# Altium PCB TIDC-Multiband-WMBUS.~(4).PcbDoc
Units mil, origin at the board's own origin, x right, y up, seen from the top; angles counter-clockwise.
Board outline 1550.5 x 1401.5 mil, 4 copper layers (1, 2, 3, 4); 57 components, 34 nets, 205 pads, 172 vias.
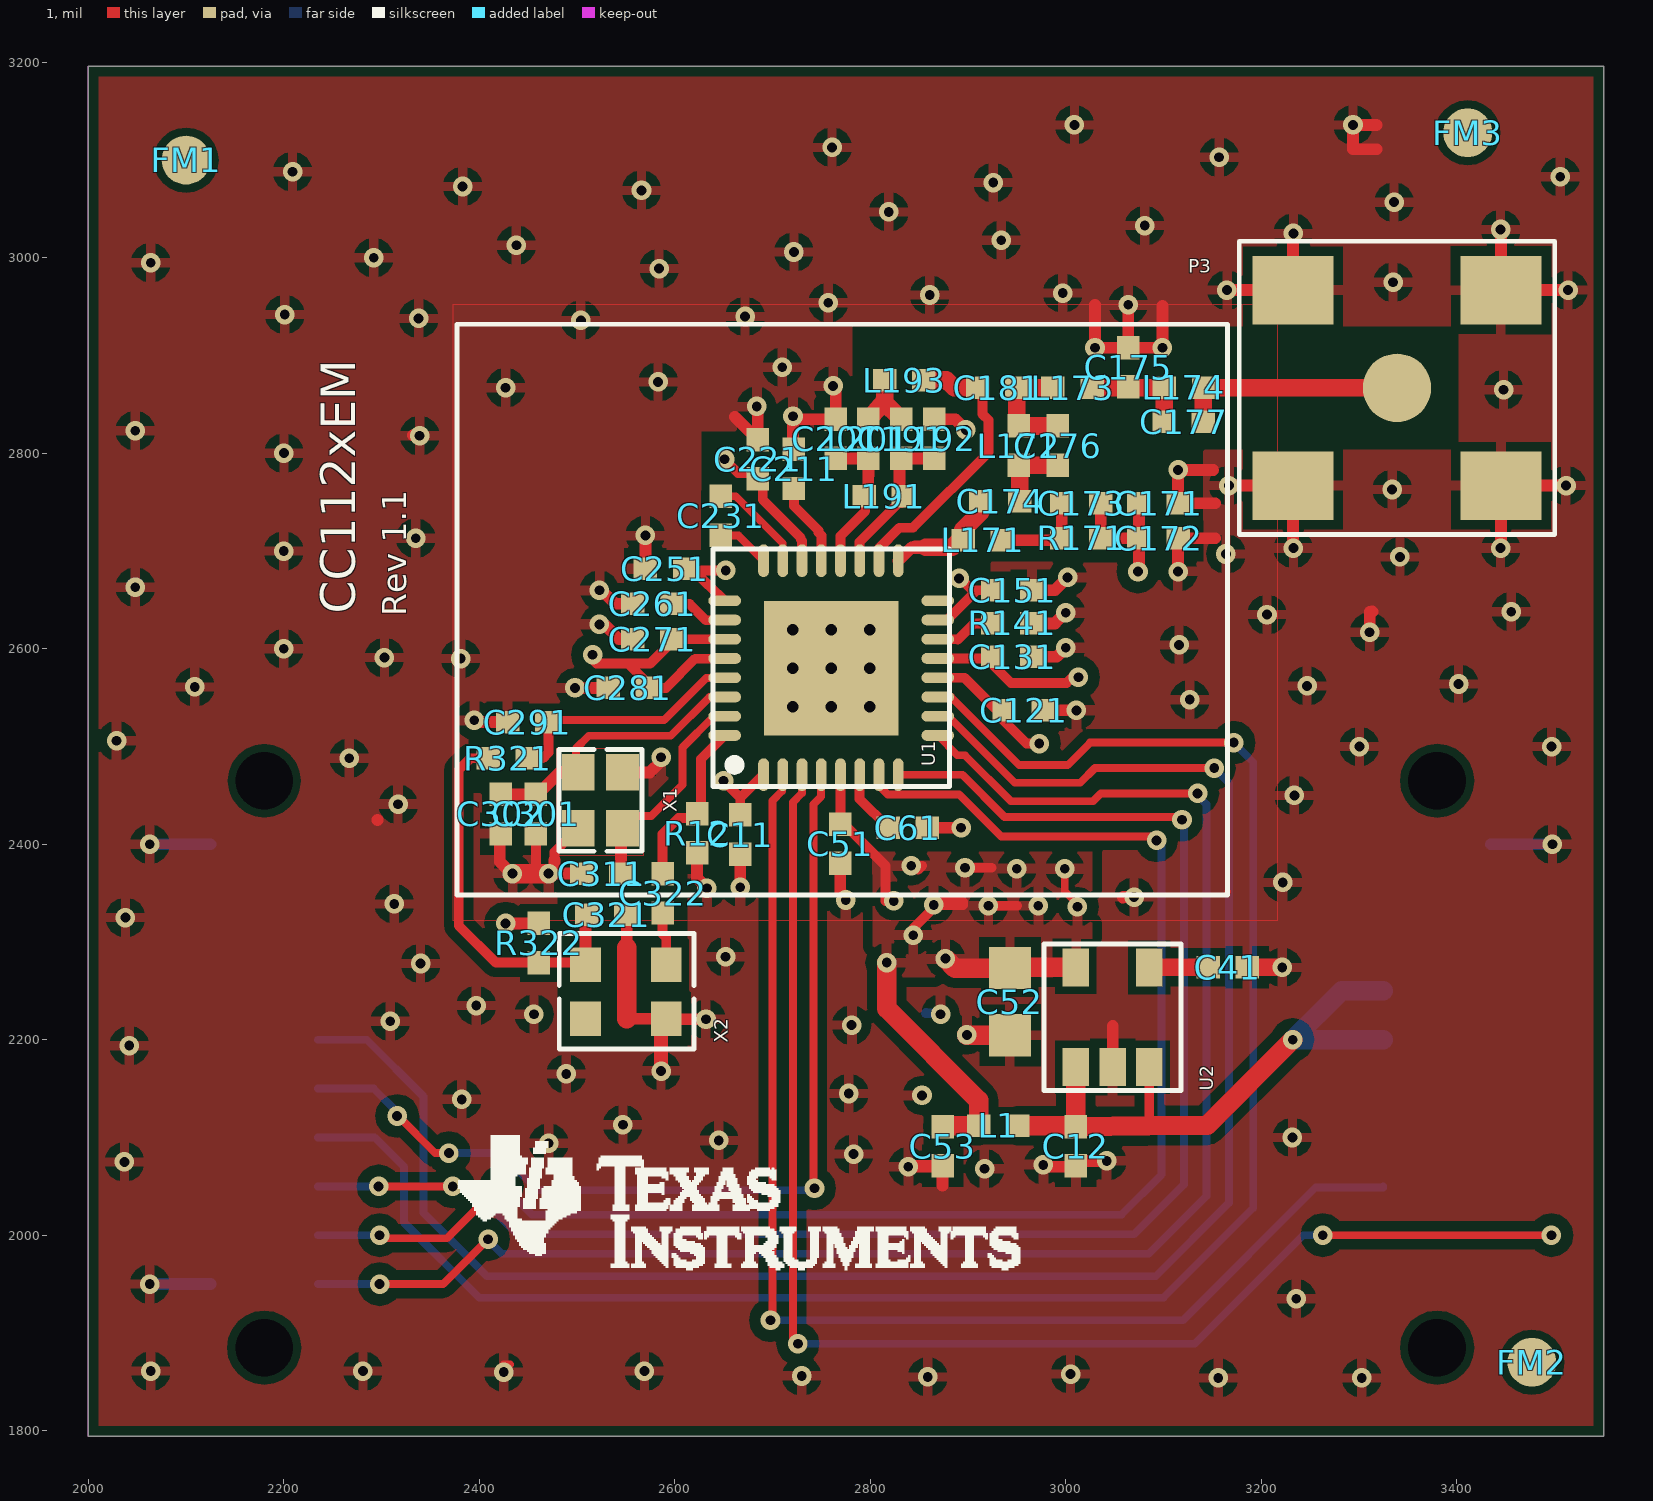
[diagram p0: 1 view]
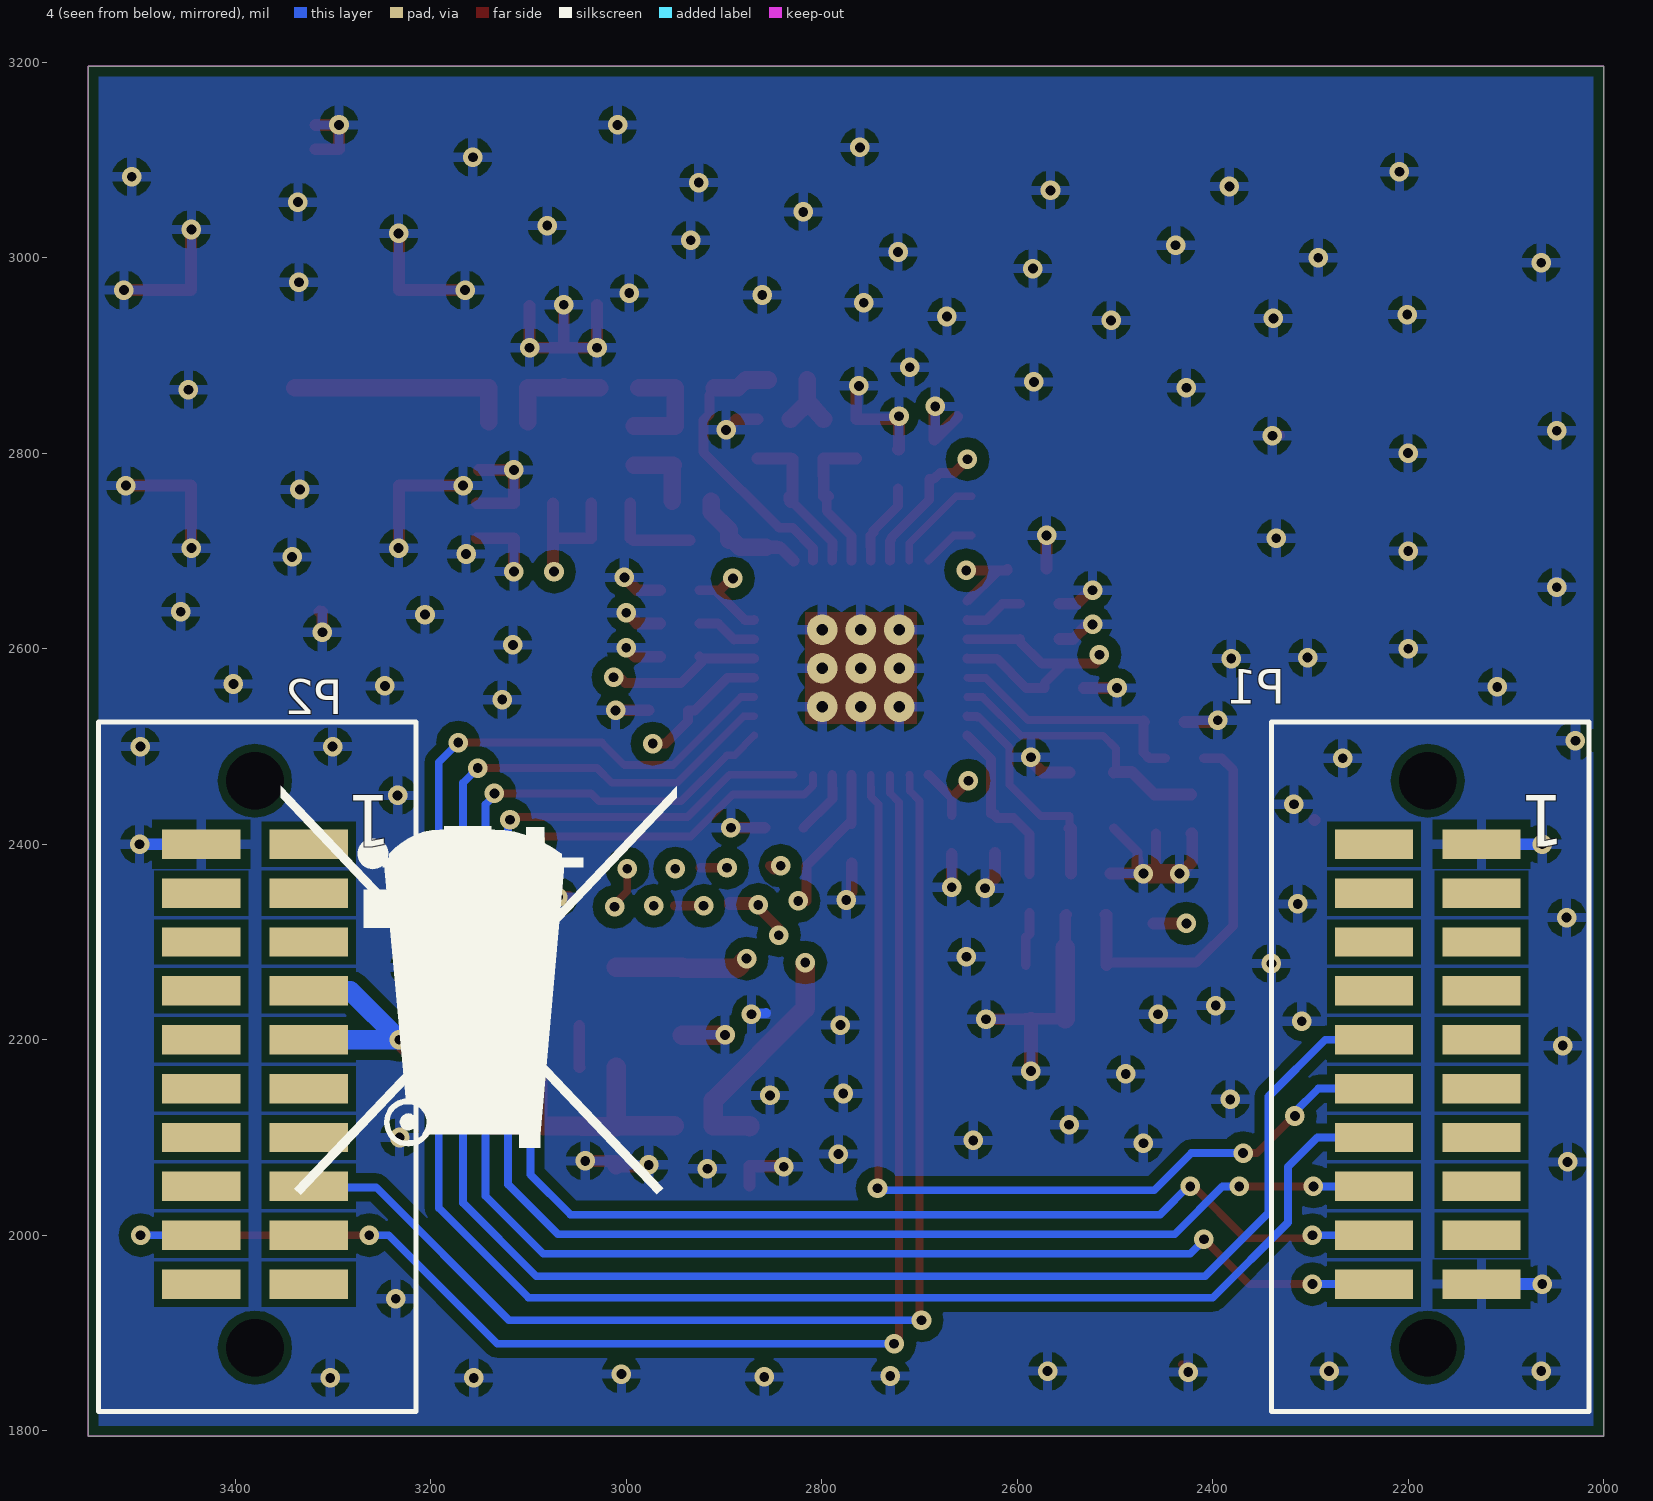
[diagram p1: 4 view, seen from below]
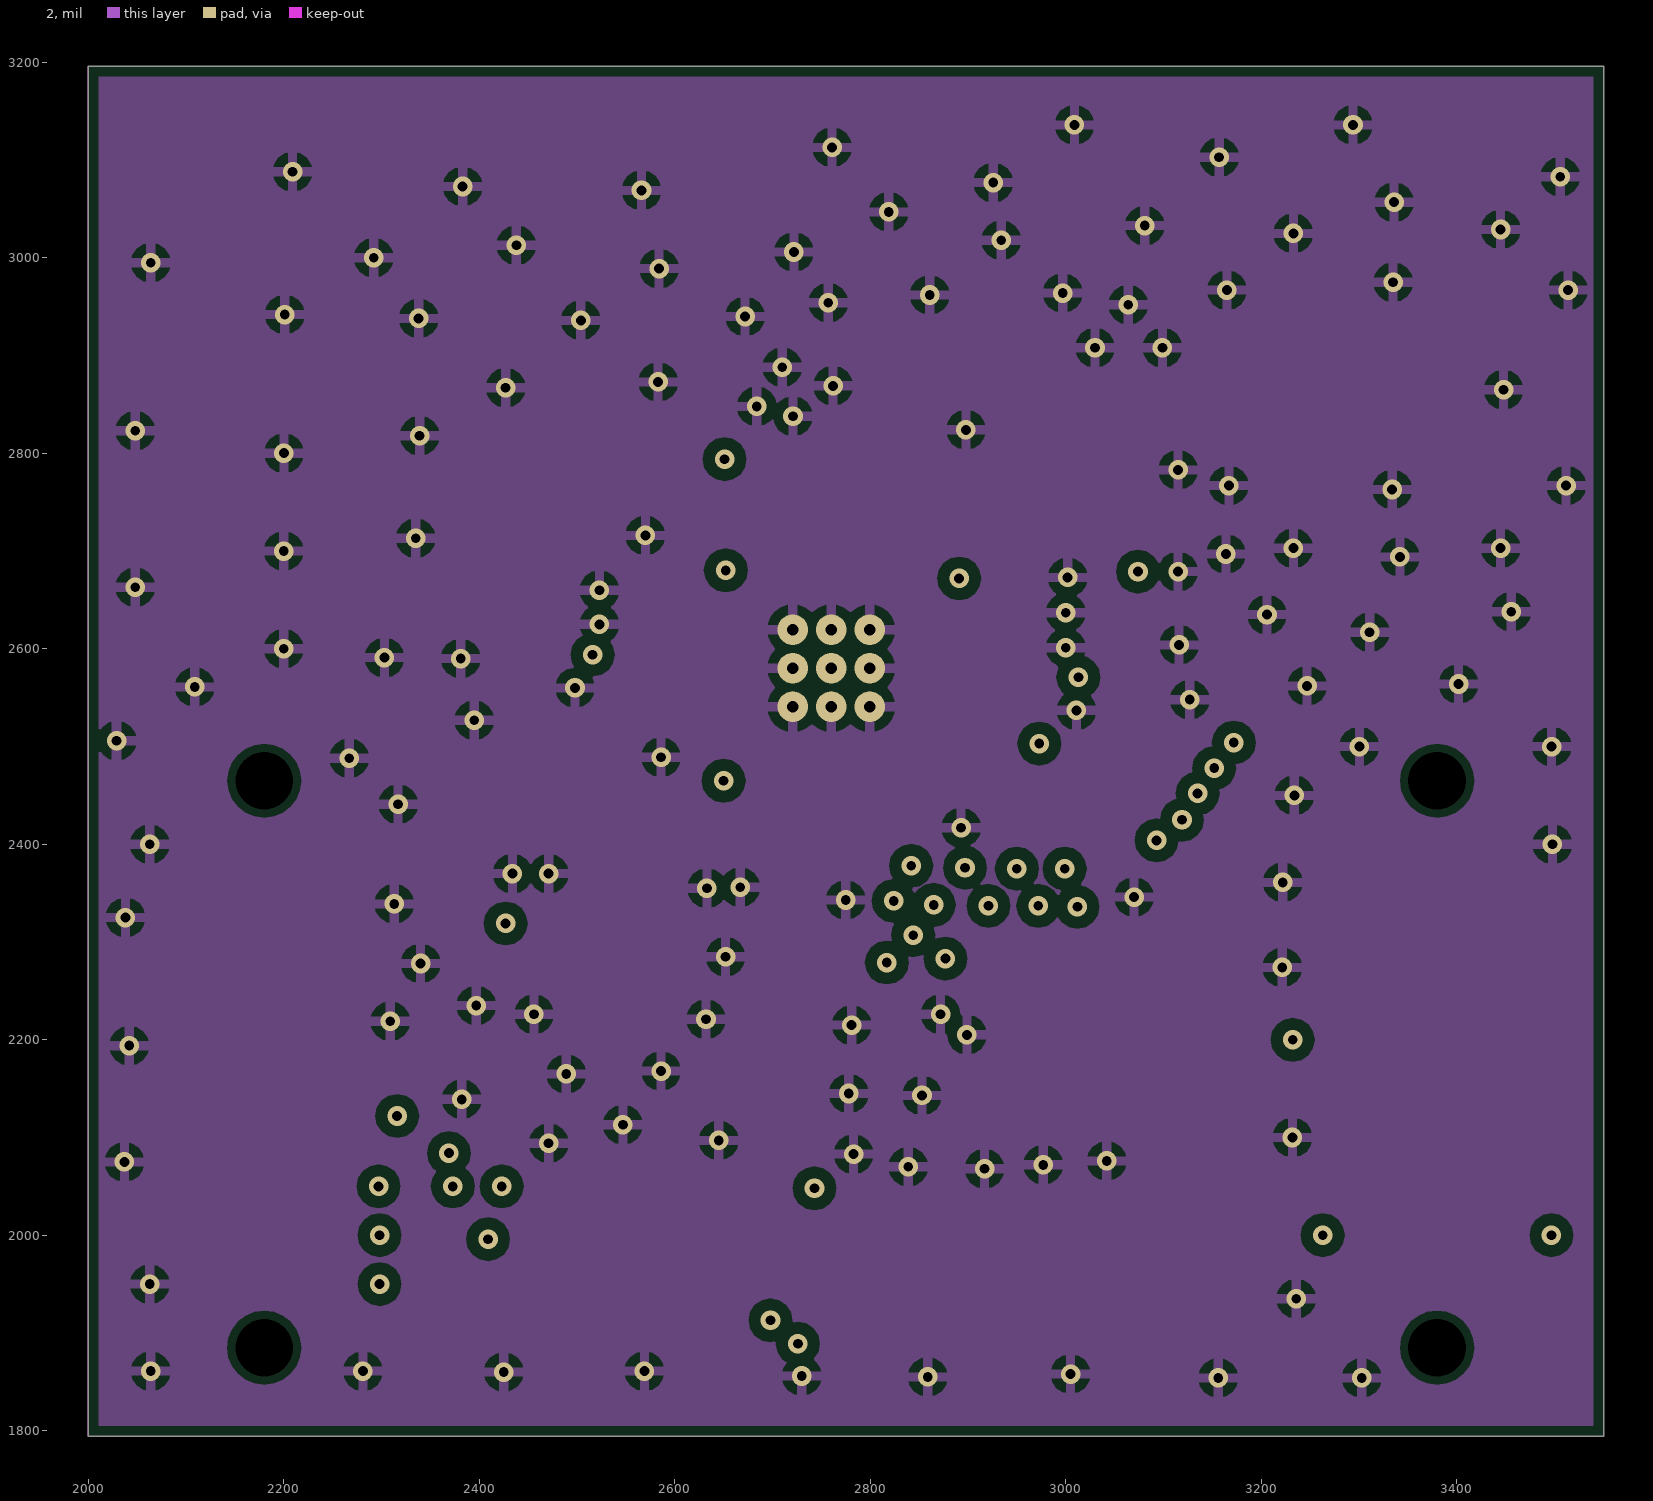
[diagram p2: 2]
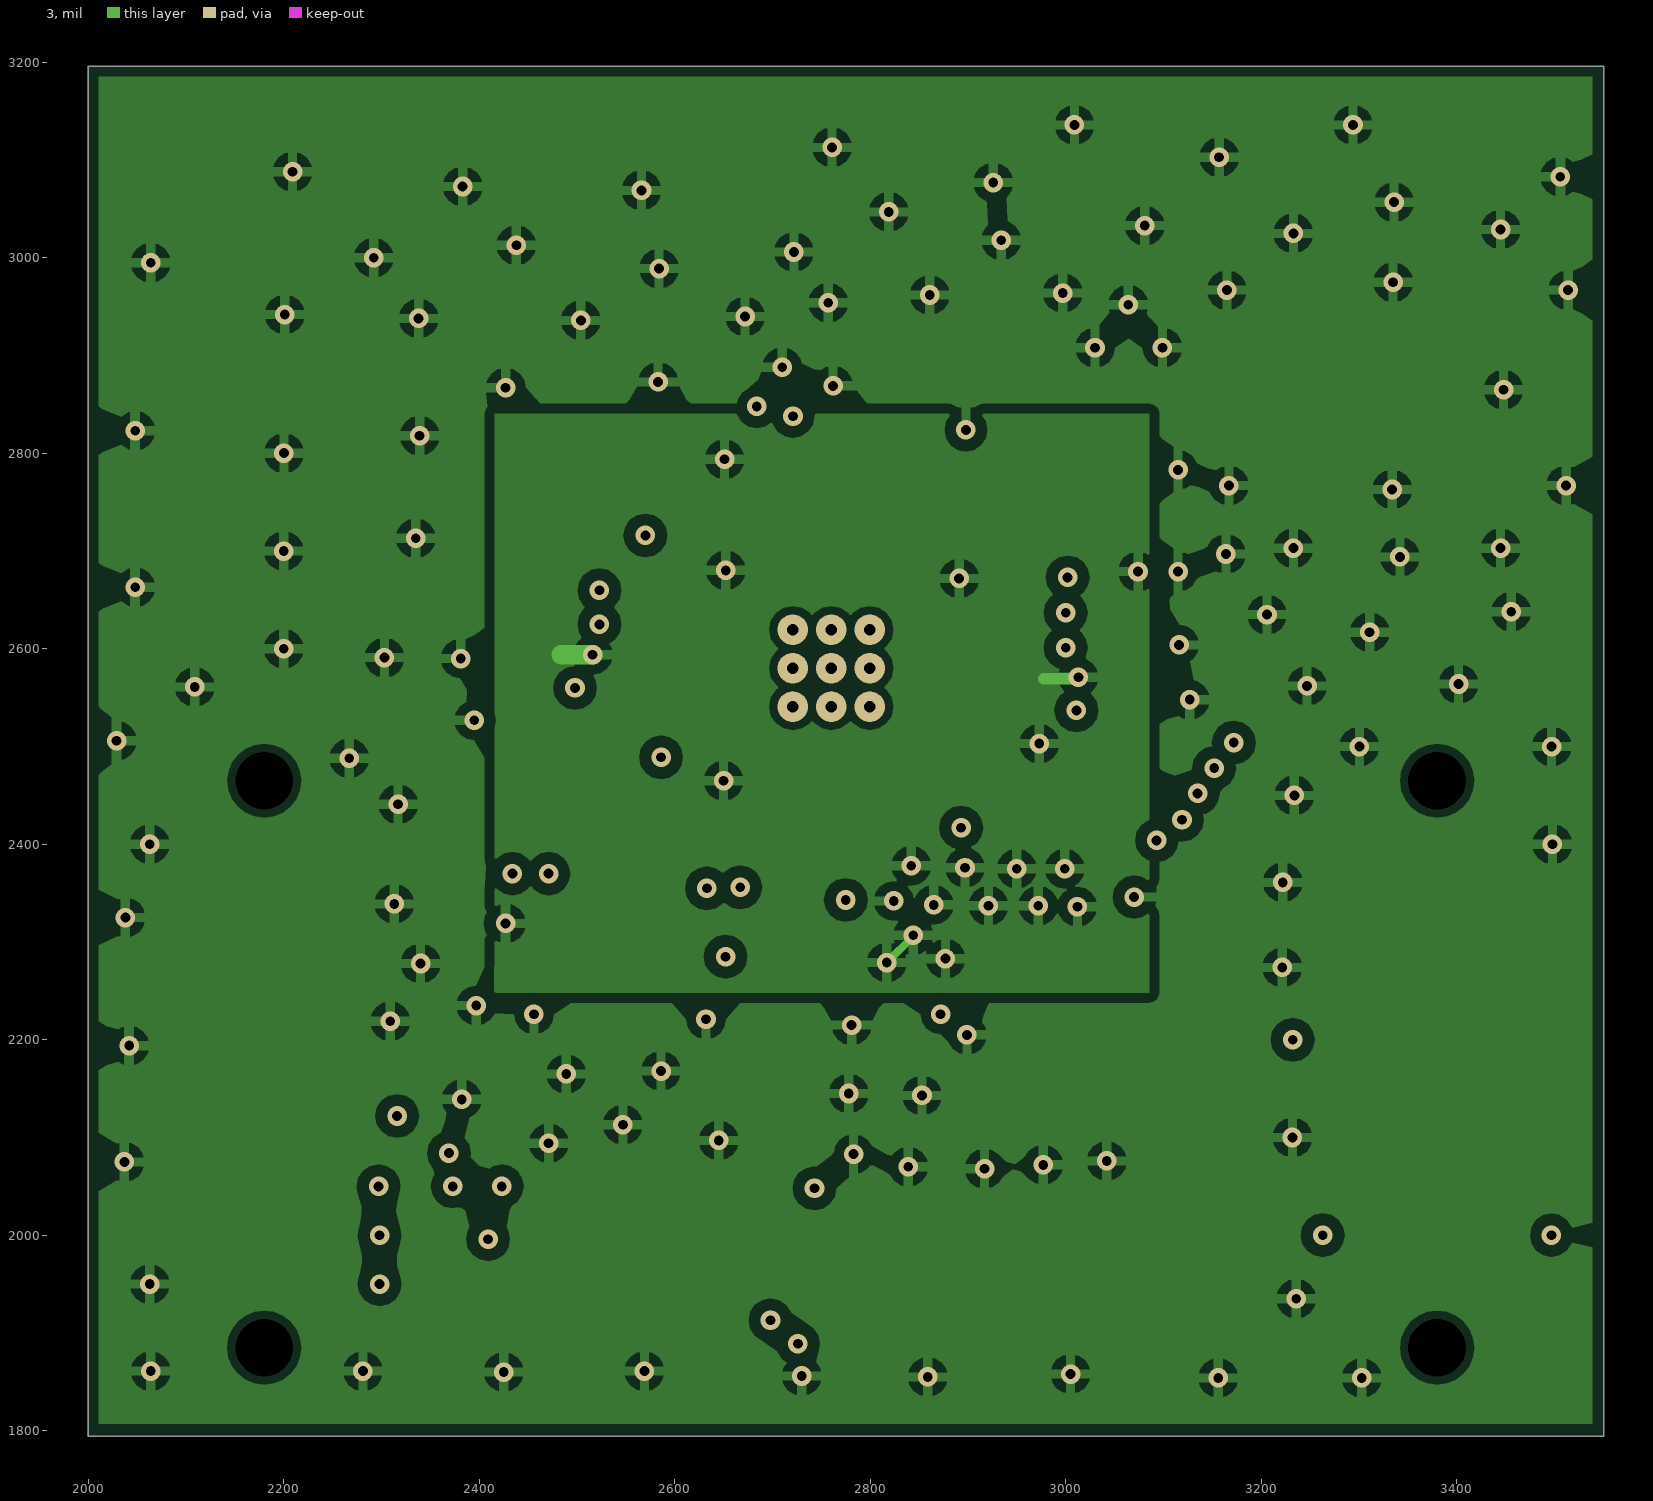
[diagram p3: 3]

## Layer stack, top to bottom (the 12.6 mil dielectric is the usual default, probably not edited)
Top Solder Resist: solder mask 0.4, Solder Resist, Dk 3.5
1: signal copper (thickness not stored)
Dielectric 1: dielectric 12.6, FR-4, Dk 4.8
2: signal copper (thickness not stored)
Dielectric2: dielectric 12.6, FR-4, Dk 4.8
3: signal copper (thickness not stored)
Dielectric3: dielectric 12.6, FR-4, Dk 4.8
4: signal copper (thickness not stored)
Bottom Solder Resist: solder mask 0.4, Solder Resist, Dk 3.5

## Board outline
2000,1794.5 3550.5,1794.5 3550.5,3196 2000,3196

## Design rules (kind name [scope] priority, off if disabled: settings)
Clearance InPolygon_L2_GND [InNamedPolygon('L2_GND') vs InNet('AGND')] p1: gap=8
Clearance InPolygon_L4_GND [InNamedPolygon('L4_GND') vs InNet('AGND')] p2: gap=8
Clearance InPolygon_L1_GND_XOSC [InNamedPolygon('L1_GND_XOSC') vs InNet('AGND')] p3: gap=8
Clearance InPolygon_L3_VDD_REG [InNamedPolygon('L3_VDD_REG') vs InNet('VDD_REG')] p4: gap=8
Clearance InPolygon_L1_GND5 [InNamedPolygon('L1_GND5') vs InNet('AGND')] p5: gap=8
Clearance InPolygon_L1_VDD_VREG [InNamedPolygon('L1_VDD_VREG') vs InNet('VDD_REG')] p6: gap=8
Clearance InPolygon_L1_GND1 [InNamedPolygon('L1_GND1') vs InNet('AGND')] p7: gap=8
Clearance InPolygon_L1_GND2 [InNamedPolygon('L1_GND2') vs InNet('AGND')] p8: gap=8
Clearance InPolygon_L3_GNE [InNamedPolygon('L3_GNE') vs InNet('AGND')] p9: gap=40
Clearance CopperToBoard [InPolygon vs (IsTrack Or IsArc) And OnLayer('Keep-out Layer')] p10: gap=10
Clearance ViaToCopper [IsVia vs InPolygon] p11: gap=12
Clearance ViaToVia [IsVia vs IsVia] p12: gap=8
Clearance PadToCopper [IsPad vs InPolygon] p13: gap=8
Clearance PadToVia [IsPad vs IsVia] p14: gap=8
Clearance PadToPad [IsPad vs IsPad] p15: gap=8
Clearance RouteToPad_1 [IsTrack or IsArc vs IsVia] p16: gap=8
Clearance RouteToPad [IsTrack Or IsArc vs IsPad] p17: gap=8
Clearance RouteToRoute [IsTrack or IsArc vs IsTrack or IsArc] p18: gap=8
Clearance [All] p19: gap=10
PolygonConnect [All] p1: connectstyle=Relief reliefconductorwidth=10 reliefentries=4 polygonreliefangle="90 Angle" airgapwidth=10
RoutingVias [All] p1: holewidth=28 width=50 viastyle="Through Hole" minholewidth=28 minwidth=50 maxholewidth=28 maxwidth=50
SolderMaskExpansion [All] p1: expansion=4
UnpouredPolygon [All] p1: allowunpoured=FALSE
Width [All] p1: maxlimit=10 minlimit=10 preferedwidth=10
29 further rules are at their usual default settings.

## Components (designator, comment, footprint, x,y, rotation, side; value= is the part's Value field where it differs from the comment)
C11 "Comment" "0402 (REFLOW LF)" 2667,2410 r90 top
C12 "Comment" "0402 (REFLOW LF)" 3010.5,2091 r270 top
C41 "Comment" "0402 (REFLOW LF)" 3165.8,2274 r0 top
C51 "Comment" "0402 (REFLOW LF)" 2769.4,2400.6 r90 top
C52 "Comment" "0603 (REFLOW)" 2943,2239 r270 top
C53 "Comment" "0402 (REFLOW LF)" 2874,2091 r270 top
C61 "Comment" "0402 (REFLOW LF)" 2838.6,2417 r0 top
C121 "Comment" "0402 (REFLOW LF)" 2957,2537 r180 top
C131 "Comment" "0402 (REFLOW LF)" 2945.25,2592 r180 top
C151 "Comment" "0402 (REFLOW LF)" 2945.5,2660 r180 top
C171 "Comment" "0402 (REFLOW LF)" 3095,2749 r0 top
C172 "Comment" "0402 (REFLOW LF)" 3095,2713 r0 top
C173 "Comment" "0402 (REFLOW LF)" 3016,2749 r0 top
C174 "Comment" "0402 (REFLOW LF)" 2933,2751 r180 top
C175 "Comment" "0402 (REFLOW LF)" 3064,2888 r90 top
C176 "Comment" "0402 (REFLOW LF)" 2992,2808 r90 top
C177 "Comment" "0402 (REFLOW LF)" 3120.8,2832.1 r0 top
C181 "Comment" "0402 (REFLOW LF)" 2930,2867 r0 top
C191 "Comment" "0402 (REFLOW LF)" 2832,2814.75 r270 top
C201 "Comment" "0402 (REFLOW LF)" 2764.75,2814.75 r90 top
C211 "Comment" "0402 (REFLOW LF)" 2722,2784 r90 top
C221 "Comment" "0402 (REFLOW LF)" 2685,2794 r90 top
C231 "Comment" "0402 (REFLOW LF)" 2647,2736 r270 top
C251 "Comment" "0402 (REFLOW LF)" 2590,2682 r0 top
C261 "Comment" "0402 (REFLOW LF)" 2577,2646 r0 top
C271 "Comment" "0402 (REFLOW LF)" 2577,2610 r0 top
C281 "Comment" "0402 (REFLOW LF)" 2552,2560 r0 top
C291 "Comment" "0402 (REFLOW LF)" 2449,2525 r0 top
C301 "Comment" "0402 (REFLOW LF)" 2458,2431 r90 top
C302 "Comment" "0402 (REFLOW LF)" 2422,2431 r90 top
C311 "Comment" "0402 (REFLOW LF)" 2525,2370 r0 top
C321 "Comment" "0402 (REFLOW LF)" 2530,2328 r180 top
C322 "Comment" "0402 (REFLOW LF)" 2587.6,2349.7 r90 top
FM1 "Comment" FIDUCAL_MARK 2100,3100 r0 top
FM2 "Comment" FIDUCAL_MARK 3477,1870 r0 top
FM3 "Comment" FIDUCAL_MARK 3411.3,3128 r0 top
L1 "Comment" "0402 (REFLOW LF)" 2931,2112 r180 top
L171 "Comment" "0402 (REFLOW LF)" 2915,2711 r0 top
L172 "Comment" "0402 (REFLOW LF)" 2952,2808 r270 top
L173 "Comment" "0402 (REFLOW LF)" 3007,2867 r180 top
L174 "Comment" "0402 (REFLOW LF)" 3121,2867 r180 top
L191 "Comment" "0402 (REFLOW LF)" 2813.75,2756 r180 top
L192 "Comment" "0402 (REFLOW LF)" 2865.75,2814.75 r270 top
L193 "Comment" "0402 (REFLOW LF)" 2835,2875 r180 top
L201 "Comment" "0402 (REFLOW LF)" 2798.25,2814.75 r270 top
P1 "Comment" "SFM SMD Socket 2x10" 2125,2400 r0 bottom
P2 "Comment" "SFM SMD Socket 2x10" 3325,2400 r0 bottom
P3 "Comment" "SMA_SMD (Extended)" 3339,2867 r0 top
R12 "Comment" "0402 (REFLOW LF)" 2622.88,2411.19 r90 top
R141 "Comment" "0402 (REFLOW LF)" 2945.25,2626 r0 top
R171 "Comment" "0402 (REFLOW LF)" 3016,2713 r0 top
R321 "Comment" "0402 (REFLOW LF)" 2429,2488 r0 top
R322 "Comment" "0402 (REFLOW LF)" 2461,2299 r90 top
U1 "Comment" "QFN32_RHM (DATASHEET)" 2710.6,2598 r90 top
U2 "Comment" SOT23-5 3048,2223 r0 top
X1 "Comment" "XTAL_SMD_2x1_6 (2.0x1.6mm no paste reduction)" 2524,2445 r90 top
X2 "Comment" "TCXO_TG_5021CG (2.5x2mm)" 2550,2249 r0 top

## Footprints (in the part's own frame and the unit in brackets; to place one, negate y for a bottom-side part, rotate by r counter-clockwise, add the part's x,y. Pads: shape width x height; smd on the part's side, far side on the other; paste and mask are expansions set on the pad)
"0402 (REFLOW LF)" [mil]
  rect 24x23 smd paste+0 mask+6: 1(-20,0) 2(20,0)
"0603 (REFLOW)" [mil]
  rect 43.31x43.31 smd paste+0 mask+4: 1(-34.38,0) 2(34.37,0)
FIDUCAL_MARK [mil]
  round 50 smd paste+0 mask+4: 1(0,0)
"QFN32_RHM (DATASHEET)" [mm]
  oval 0.85x0.28 smd paste+0 mask+0.14: 1(-3.221,0.5) 2(-3.221,0) 3(-3.221,-0.5) 4(-3.221,-1) 5(-3.221,-1.5) 6(-3.221,-2) 7(-3.221,-2.5) 8(-3.221,-3) 17(2.342,-3) 18(2.342,-2.5) 19(2.342,-2) 20(2.342,-1.5) 21(2.342,-1) 22(2.342,-0.5) 23(2.342,0) 24(2.342,0.5)
  oval 0.28x0.85 smd paste+0 mask+0.14: 9(-2.2,-4.027) 10(-1.7,-4.027) 11(-1.2,-4.027) 12(-0.7,-4.027) 13(-0.2,-4.027) 14(0.3,-4.027) 15(0.8,-4.027) 16(1.3,-4.027) 25(1.3,1.51) 26(0.8,1.51) 27(0.3,1.51) 28(-0.2,1.51) 29(-0.7,1.51) 30(-1.2,1.51) 31(-1.7,1.51) 32(-2.2,1.51)
  rect 3.5x3.5 smd paste-3.5 mask+0: 33(-0.452,-1.259)
  round 0.8 hole 0.3 paste+0 mask+0: 34(-1.452,-0.259) 35(-1.452,-1.259) 36(-1.452,-2.259) 37(-0.452,-0.259) 38(-0.452,-1.259) 39(-0.452,-2.259) 40(0.548,-0.259) 41(0.548,-1.259) 42(0.548,-2.259)
  rect 1.1x1.1 smd paste+0 mask+0: 43(-1.239,-0.472) 44(-1.239,-2.047) 45(0.336,-0.472) 46(0.336,-2.047)
  1 region: -1.9,-2.7 1,-2.7 1,0.2 -1.9,0.2
  1 region: -1.9,-2.7 1,-2.7 1,0.2 -1.9,0.2
  1 region: -1.9,-2.7 1,-2.7 1,0.2 -1.9,0.2
  1 region: -1.9,-2.7 1,-2.7 1,0.2 -1.9,0.2
  1 region: -1.9,-2.7 1,-2.7 1,0.2 -1.9,0.2
  1 region: -1.9,-2.7 1,-2.7 1,0.2 -1.9,0.2
  1 region: -1.9,-2.7 1,-2.7 1,0.2 -1.9,0.2
  1 region: -1.9,-2.7 1,-2.7 1,0.2 -1.9,0.2
  1 region: -1.9,-2.7 1,-2.7 1,0.2 -1.9,0.2
  1 region: -1.9,-2.7 1,-2.7 1,0.2 -1.9,0.2
  1 region: -1.9,-2.7 1,-2.7 1,0.2 -1.9,0.2
  1 region: -1.9,-2.7 1,-2.7 1,0.2 -1.9,0.2
  1 region: -1.9,-2.7 1,-2.7 1,0.2 -1.9,0.2
  silkscreen extent -3.53,-4.33 2.65,1.81
"SFM SMD Socket 2x10" [mil]
  rect 80x30 smd paste-2 mask+4: 1(0,0) 2(110,0) 3(0,50) 4(110,50) 5(0,100) 6(110,100) 7(0,150) 8(110,150) 9(0,200) 10(110,200) 11(0,250) 12(110,250) 13(0,300) 14(110,300) 15(0,350) 16(110,350) 17(0,400) 18(110,400) 19(0,450) 20(110,450)
  round 5 hole 59 paste+0 mask+64: 21(55,-65) 22(54.96,515)
  silkscreen extent -110,-125 215,581
"SMA_SMD (Extended)" [mm]
  round 1.778 smd paste+0 mask+0.076: 1(0,0)
  rect 2.1x1.78 smd paste+0 mask+0.07: 2(2.7,-2.54) 3(-2.7,-2.54) 4(-2.7,2.54) 5(2.7,2.54)
  silkscreen extent -4.1,-3.81 4.1,3.81
SOT23-5 [mil]
  rect 27x39 smd paste+0 mask+0: 1(-37.5,-51) 2(0,-51) 3(37.5,-51) 4(37.5,51) 5(-37.5,51)
  silkscreen extent -70,-75 70,75
"TCXO_TG_5021CG (2.5x2mm)" [mm]
  rect 0.8x0.9 smd paste-0.1 mask+0.1: 1(-1.05,-0.7) 2(1.05,-0.7) 3(1.05,0.7) 4(-1.05,0.7)
  silkscreen extent -1.73,-1.48 1.77,1.52
"XTAL_SMD_2x1_6 (2.0x1.6mm no paste reduction)" [mil]
  rect 37.5x33.5 smd paste+0 mask+3.9: 1(-28.54,-22.64) 2(28.54,-22.64) 3(28.54,22.64) 4(-28.54,22.64)
  silkscreen extent -52,-43 52,42

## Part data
C11 C51 C121 C131 C151 C221 C251 C261 C271 C281 C291: library part C_47N_0402_X7R_K_25, "Capacitor 0402"
C12 C321: library part C_100N_0402_X5R_K_10, "Capacitor 0402"
C41 C171 C211: library part C_10N_0402_X7R_K_25, "Capacitor 0402"
C52: library part C_2U2_0603_X5R_K_10, "Capacitor 0603"
C53 C177 C302: library part C_0402, "Capacitor 0402, general"
C61: library part C_220N_0402_X5R_K_10, "Capacitor 0402"
C172: library part C_100P_0402_NP0_J_50, "Capacitor 0402"
C173: library part C_33P_0402_NP0_J_50, "Capacitor 0402"
C174 C301 C311: library part C_15P_0402_NP0_J_50, "Capacitor, 0402"
C175: library part C_3P0_0402_NP0_C_50, "Capacitor 0402"
C176: library part C_1P0_0402_NP0_B_50, "Capacitor, 1p, 0402, NP0, +/-0.1pF 50V"
C181: library part C_2P2_0402_NP0_C_50, "Capacitor 0402"
C191 C201: library part C_3P3_0402_NP0_C_50, "Capacitor 0402"
C231: library part C_1N8_0402_U2J_J_10, "Capacitor 0402"
C322: library part C_22P_0402_NP0_J_50, "Capacitor 0402"
FM1 FM2 FM3: library part FIDUCIAL_MARK, "Fiducial mark"
L1: library part L_BEAD_102_0402, "EMI filter bead, BLM15HG102SN1D"
L171: library part L_10N_0402_J_LQW, "Inductor, 10nH, 0402, Wire-wound type, +/-5 %"
L172: library part L_7N5_0402_G_LQW, "Inductor, 7.5nH, 0402, Wire-wound type, +/-2%"
L173: library part L_18N_0402_J_LQW, "Inductor, 18nH, 0402, Wire-wound type, +/- 5%"
L174 L192 L193 L201: library part L_12N_0402_J_LQW, "Inductor, 12nH, 0402, Wire-wound type, +/-5 %"
L191: library part L_15N_0402_J_LQW, "Inductor, 15nH, 0402, Wire-wound type, +/- 5%"
P1 P2: library part SMD_SOCKET_2X10, "SMD pinrow socket, .050 spacing, SFM-110-02-SM-D-A-K-TR"
P3: library part SMA_SMD, "Surface-mount SMA, straight"
R12 R321: library part R_0402, "Resistor 0402, general"
R141: library part R_56K_0402_F, "Resistor 0402"
R171: library part R_10_0402_J, "Resistor 0402"
R322: library part R_0_0402, "Resistor, 0402"
U1: library part CC112X, "High performance narrow band tranceiver"
U2: library part TPS79930, "LDO 3V low noise"
X1: library part X_32.000/10/20/60/10, "Epson Toyocom FA128 32 MHz 2x1.6mm 10 pF, -40/85C, Q22FA1280009200"
X2: library part TG_5021CG, "EpsonToyocom miniature size TCXO 2.5x2.0mm"

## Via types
v1: diameter 20, hole 10, 1 to 4, 172 vias

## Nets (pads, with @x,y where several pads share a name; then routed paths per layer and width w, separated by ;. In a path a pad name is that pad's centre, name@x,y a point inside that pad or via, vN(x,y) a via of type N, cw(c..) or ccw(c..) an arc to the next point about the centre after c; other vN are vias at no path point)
3V3A: C12.1 L1.1 P2.7 P2.9 U2.1 U2.3 | length 646.2
  1 w10: 3084,2111.9 3085.5,2111.9 U2.3
  1 w20: L1.1 C12.1@3010.5,2112 ; U2.1 C12.1@3010.5,2112 ; v1(3232.3,2200) 3144.95,2112.65 3084,2111.9 C12.1 C12.1@3010.5,2112
  4 w20: P2.9 v1(3232.3,2200) 3282.3,2250 P2.7
87: C61.1 U1.6 | length 66.4
  1 w10: U1.6 2789.19,2446.41 C61.1
107: C211.1 U1.21 | length 85.5
  1 w10: C211.1 2722,2746.02 2747,2721.02 2747,2719 2750.18,2715.82 U1.21
110: C231.1 U1.23 | length 101.2
  1 w8: C231.1 2662.53,2756 2710.45,2708.08 2710.45,2698.31 U1.23
147: C291.2 R321.2 U1.29 | length 258.4
  1 w8: C291.2@2471,2527 2589,2527 2632.21,2570.21 2649,2570.21 U1.29
  1 w10: R321.2 2465,2488 2471,2494 2471,2527 C291.2
149: C261.2 U1.26 | length 61.1
  1 w10: C261.2 2615,2646 2631.69,2629.31 U1.26
192: C41.1 U2.4 | length 60.3
  1 w18: U2.4 C41.1
204: C311.2 U1.31 X1.1 | length 229.5
  1 w8: X1.1 2546.64,2429 2576,2429 2608,2461 2608,2499 2639.49,2530.49 U1.31@2641,2530.49
  1 w10: U1.31@2641,2530.49 U1.31
  1 w12: C311.2 2545,2416.46 X1.1
205: C301.2 C302.2 U1.30 X1.3 | length 287
  1 w8: X1.3@2499,2474 2499,2498 2512,2511 2596,2511 2635.54,2550.54 2650,2550.54 U1.30
  1 w12: C302.2 C301.2 2460,2451 2483,2474 2499,2474 2500.91,2474 X1.3
214: C321.2 R321.1 R322.1 X2.4 | length 392.2
  1 w10: R321.1 2391,2488 2379,2476 2379,2316.88 2416.88,2279 R322.1 X2.4@2508.66,2279
  1 w12: X2.4 2508.66,2279 2508.66,2328 C321.2
217: C191.2 L191.1 L192.2 U1.19 | length 166.1
  1 w10: U1.19 2789.19,2709.19 L191.1@2830,2750 ; L191.1@2832,2750 2834,2752 2834,2756 L191.1
  1 w12: L191.1@2832,2750 2830,2750 2830,2794.5 C191.2 L192.2
219: C201.1 L191.2 L201.2 U1.20 | length 152.9
  1 w10: U1.20 2769.5,2715.5 2795,2741 L191.2@2795,2756
  1 w12: C201.1 L201.2 2798,2756 2795,2756 L191.2
221: C191.1 L193.2 L201.1 | length 72
  1 w18: L201.1 2813.92,2852.58 ; L193.2 2815,2853.65 2813.92,2852.58 ; C191.1 2813.92,2852.58
222: C174.2 L171.1 U1.17 | length 122.4
  1 w12: U1.17 2842.56,2704 2846,2704
  1 w14: 2846,2704 2857,2704
  1 w18: 2857,2704 2884,2704 2891,2711 L171.1 2895,2721.77 2913,2739.77 C174.2
223: C181.1 L193.1 U1.18 | length 295.1
  1 w10: U1.18 2809,2702.87 2830.06,2723.94 2843.94,2723.94 2921,2801 2921,2834 2915,2840 2915,2860 C181.1@2908,2867
  1 w18: L193.1 2878,2875 2886,2867 2908,2867 C181.1
224: C176.2 C181.2 L172.1 L173.2 | length 118
  1 w18: L173.2 C181.2 2950,2828 L172.1 C176.2
228: C231.2 U1.24 | length 54.6
  1 w8: C231.2 2665.1,2716 U1.24
243: R141.1 U1.14 | length 62.9
  1 w10: U1.14 2889.62,2609.62 2906,2626 R141.1
258: C322.1 X2.3 | length 54.7
  1 w10: C322.1 2587.6,2308.4 2591.34,2304.66 X2.3
259: C322.2 R12.2 U1.32 | length 181.1
  1 w10: C322.2 2587.6,2410.6 2604,2427 2620.81,2427 R12.2@2625,2431.19 ; R12.2 R12.2@2625,2431.19 ; U1.32 2627,2487.2 2627,2431.19 R12.2@2625,2431.19
278: C173.1 L171.2 R171.1 | length 98.2
  1 w12: L171.2 2993,2711 R171.1@2996,2714 ; R171.1 R171.1@2996,2714 ; C173.1 R171.1@2996,2714
279: C174.1 C176.1 L172.2 | length 77
  1 w18: L172.2 L172.2@2953,2788 ; C174.1 L172.2@2953,2788 ; C176.1 L172.2@2953,2788
280: C177.2 L174.1 P3.1 | length 237.1
  1 w18: C177.2 3140.8,2867 L174.1@3145,2867 ; L174.1 L174.1@3145,2867 ; P3.1 L174.1@3145,2867
282: C175.1 C177.1 L173.1 L174.2 | length 109.9
  1 w18: L173.1 C175.1@3064,2867 ; C175.1 C175.1@3064,2867 ; C177.1 L174.2@3100.8,2867 ; L174.2 L174.2@3100.8,2867 ; C175.1@3064,2867 L174.2@3100.8,2867
AGND: C11.1 C12.2 C41.2 C51.1 C52.2 C53.2 C61.2 C121.1 C131.1 C151.1 C171.2 C172.2 C175.2 C201.2 C211.2 C221.2 C251.1 C261.1 C271.1 C281.1 C291.1 C301.1 C302.1 C311.1 C321.1 L192.1 P1.1 P1.19 P2.2 P3.2 P3.3 P3.4 P3.5 R12.1 R141.2 U1.33 U1.34 U1.35 U1.36 U1.37 U1.38 U1.39 U1.40 U1.41 U1.42 U1.43 U1.44 U1.45 U1.46 U2.2 X1.2 X1.4 X2.2 | length 2795.8
  1 w8: v1@2063.68,1861.41 v1(2064,1861) ; v1@2063.68,2995.06 2064,2995.06 v1(2064,2995) ; v1@2208.81,3087.99 v1(2209,3088) ; v1@2431,1860 v1(2425,1860) 2425,1867.86 2431.35,1867.86 ; v1(2730,1856) 2730,1855.94 2730.06,1855.94 v1@2730.49,1856.37 ; v1(3005,1858) 3005,1858.11 3005.11,1858.11 v1@3005.44,1857.78 ; U2.2@3048.27,2172 U2.2@3048.27,2172.27 ; 3048.27,2214 3048.27,2216.18 ; v1@3231.56,2099.52 v1(3232,2100) ; v1@3235.63,1935.38 v1(3236,1935)
  1 w10: 2458,2370 C301.1 ; 2477,2384 2477,2392.09 X1.4
  1 w12: 2295.87,2424.66 2295.87,2425 ; v1@2308.78,2219.15 v1(2309,2219) ; v1(2317,2441) 2317,2440.92 2316.92,2440.92 v1@2317.2,2440.63 ; v1@2332.11,2818.39 2339,2818.39 v1(2339,2818) ; v1@2334.83,2712.87 v1(2335,2713) ; v1(2338,2938) 2338,2937.94 2337.94,2937.94 v1@2338.16,2937.72 ; v1(2340,2278) 2340,2277.87 2340.13,2277.87 v1@2340.46,2278.2 ; v1(2381,2590) 2381,2589.85 2381.15,2589.85 v1@2381.5,2590.21 ; v1(2395,2527) 2395,2525 C291.1 ; C302.1 2421,2411 2421,2382 2433,2370 v1(2434,2370) ; v1@2455.82,2226.86 2455.98,2227.02 v1(2456,2226) ; 2458,2370 v1(2471,2370) v1@2477,2370 ; 2477,2384 v1@2477,2370 ; v1(2489,2165) 2489,2164.93 v1@2489.29,2164.93 ; v1(2498,2560) C281.1 ; C311.1 v1@2477,2370 ; v1(2523,2625) 2528,2625 2543,2610 C271.1 ; v1(2523,2660) 2523,2662 2539,2646 C261.1 ; X1.2 2574.54,2473.54 2586,2485 v1(2586,2489) ; C321.1 2551,2327 2551,2294 ; 2551,2221.44 2586,2221.44 X2.2 2591.34,2221 v1(2632,2221) v1@2632,2221.44 ; C251.1 v1(2570,2716) ; v1(2583,2873) 2583,2873.07 2582.93,2873.07 v1@2583.28,2873.42 ; v1@2583.88,2989.12 v1(2584,2989) ; R12.1 2622.88,2365.12 v1(2633,2355) ; v1@2651.86,2285.37 2651.86,2285 v1(2652,2285) ; 2661.5,2837.5 C221.2 2685,2847 v1(2684,2848) v1@2684,2842 ; v1(2667,2356) C11.1 ; v1@2709.86,2887.93 v1(2710,2888) ; v1(2721,2838) v1@2721,2834.75 ; C211.2 2721,2804 v1@2721,2834.75 ; v1(2757,2954) v1@2757.04,2954.35 ; v1(2761,3113) 2761,3113.07 2760.94,3113.07 v1@2761.27,3113.4 ; v1(2762,2869) 2762,2865 v1@2764.75,2865 ; v1@2764.75,2868 C201.2 v1@2721,2834.75 ; C51.1 2769.4,2351.6 2775,2346 v1(2775,2343) ; v1(2778,2145) v1@2778.24,2145.17 ; v1@2782.58,2083.29 2782.93,2082.93 2783,2082.93 v1(2783,2083) ; v1@2818.61,3047.48 v1(2819,3047) ; C61.2 v1(2893,2417) ; v1(2861,2962) 2861,2962.08 2860.92,2962.08 v1@2861.25,2962.42 ; L192.1 2887.25,2834.75 v1(2898,2824) ; 2874,2051 2874,2070 v1(2839,2070) 2839,2071 C53.2 ; C131.1 2991,2592 v1(3000,2601) ; R141.2 2989,2626 v1(3000,2637) ; C151.1 2989,2660 v1(3002,2673) ; v1(2977,2072) 2977,2070 3010.5,2070 C12.2 ; C121.1 v1(3011,2537) ; C12.2@3010.5,2075 3010.5,2076 v1(3042,2076) ; 3030,2952 v1(3030,2908) C175.2 ; U2.2 3048.27,2172.27 3048.27,2214 ; 3058.53,2345.54 3059,2346 v1(3070,2346) ; v1(3064,2952) C175.2 ; v1(3081,3033) v1@3081.17,3032.87 ; 3099,2951 v1(3099,2908) C175.2 ; v1(3115,2679) C172.2 3153,2713 ; v1(3116,2604) 3116,2603.92 3115.92,2603.92 v1@3116.14,2603.71 ; v1@3126.72,2547.98 v1(3127,2548) ; 3151,2783 v1(3115,2783) C171.2 3153,2749 ; v1@3163.91,2697.35 3163.91,2697 v1(3164,2697) ; v1(3165,2967) P3.4 3232.7,3025 v1(3233,3025) ; v1(3167,2767) P3.3 3232.7,2703 v1(3233,2703) ; v1@3206.04,2634.85 v1(3206,2635) ; v1(3247,2562) 3247,2562.11 3246.89,2562.11 v1@3247.27,2562.48 ; v1(3311,2617) 3311,2637.93 3313.93,2637.93 ; 3313.68,2638.18 3313.93,2637.93 ; 3314,2638 3314,2637.93 3313.93,2637.93 ; 3318,3136 v1(3294,3136) 3294,3110.98 3318.02,3110.98 3318.22,3111.18 ; v1(3334,2763) 3334,2762.95 3333.95,2762.95 v1@3334.34,2762.55 ; v1(3335,2975) 3335,2974.88 3335.12,2974.88 v1@3335.45,2975.22 ; v1(3336,3057) 3336,3056.89 3336.11,3056.89 v1@3336.48,3057.26 ; v1(3402,2564) 3402.08,2564 v1@3402.08,2564.2 ; v1(3445,2703) 3445.3,2703 P3.2 v1(3512,2767) ; v1(3445,3029) 3445.3,3029 P3.5 v1(3514,2967) ; v1@3455.9,2638.18 v1(3456,2638)
  1 w14: v1(2586,2168) X2.2@2586,2221.44
  1 w18: C12.2 C12.2@3010.5,2072 ; C41.2 v1(3221.5,2274)
  1 w20: v1(2434,2370) v1(2471,2370) ; 2551,2221.44 2551,2294 ; v1(2899,2205) 2899,2204.63 C52.2 ; v1(3222,2361) v1@3222,2361.1
  4 w8: v1@2036.87,2075.28 2037.07,2075.07 2037,2075.07 v1(2037,2075) ; v1@2108.58,2560.52 v1(2109,2561) ; v1(2201,2942) 2201,2941.9 2200.9,2941.9 v1@2201.15,2941.64 ; v1(2281,1861) v1@2281.38,1861.41 ; v1@2291.61,2999.95 v1(2292,3000) v1(2292,3000) ; v1(2383,3073) 2383,3072.92 2382.92,3072.92 v1@2383.17,3072.67 ; v1(2859,1855) v1@2859.09,1855.16 ; v1@3155.61,1853.95 3156,1853.95 v1(3156,1854) ; v1(3303,1854) 3303,1853.95 v1@3303.16,1853.95
  4 w10: v1(2267,2488) 2267,2488.15 v1@2267.42,2488.15 ; 2857.23,2227.31 2856.96,2227.04 2872,2227.04 v1(2872,2226)
  4 w12: v1(2063,1950) P1.19 ; v1(2063,2400) P1.1 ; v1(2303,2591) v1@2303,2592.02 ; v1@2313.01,2338.58 v1(2313,2339) ; v1@2381.85,2139.12 v1(2382,2139) ; v1(2397,2235) 2397,2234.94 2396.94,2234.94 v1@2397.27,2234.62 ; v1(2427,2867) 2427.06,2867 v1@2427.06,2866.67 ; v1(2438,3013) v1@2438.44,3012.51 ; v1(2471,2094) 2471,2094.07 2470.93,2094.07 v1@2471.24,2094.38 ; v1@2503.65,2936.11 2504,2936.11 v1(2504,2936) ; v1@2546.94,2113.32 2546.94,2113 v1(2547,2113) ; v1@2565.84,3069.05 v1(2566,3069) ; v1(2645,2097) v1@2644.96,2097.36 ; v1@2671.57,2940.04 v1(2672,2940) ; v1(2853,2143) v1@2853.03,2143.46 ; v1(2926,3077) v1@2926.15,3076.81 ; v1(2934,3018) v1@2934.12,3018.05 ; v1(2997,2964) 2997,2963.87 2996.87,2963.87 v1@2997.21,2963.52 ; v1@3008.5,3136.07 3009,3136.07 v1(3009,3136) ; v1@3156.66,3103.42 v1(3157,3103) ; v1(3342,2694) v1@3342.33,2694.03 ; P2.2 v1(3498,2400) ; v1(3448,2865) 3448,2865.06 3447.94,2865.06 v1@3448.13,2865.26 ; v1(3506,3083) v1@3506.39,3083.46
  4 w20: v1(2048,2663) v1@2048.23,2663.26 ; v1(2722,3006) v1@2722.09,3006.14 ; v1(3234,2450) 3234,2450.05 3233.95,2450.05 v1@3234.09,2450.19
  other v1: 2569,1861 2917,2068 2042,2194 2781,2215 2038,2325 3300.53,2500 3497.17,2500 2029,2506 2199.92,2600.08 2200.02,2700 2200.21,2800.21 2048,2823
CSN: P1.14 U1.11 | length 1921.9
  1 w8: U1.11 2882.96,2550.57 2952.53,2481 3002,2481 3025,2504 v1(3172,2504)
  4 w8: P1.14 2293,2100 2323,2070 2323,2013 2400,1936 3100,1936 3192,2028 3192,2484 v1(3172,2504)
GPIO0: P1.10 U1.10 | length 1901.4
  1 w8: U1.10 2880.02,2530.88 2947.9,2463 3015,2463 3030,2478 v1(3152,2478)
  4 w8: P1.10 2285,2200 2343,2142 2343,2023 2408,1958 3092,1958 3167,2033 3167,2463 v1(3152,2478)
GPIO2: P1.12 U1.4 | length 989.7
  1 w8: v1(2316,2122) 2317,2122 2355,2084 v1(2369,2084) ; v1(2743,2048) 2740,2048 2742,2046 2742,2441 2749.82,2448.82 U1.4
  4 w8: P1.12 2292,2150 2316,2126 v1(2316,2122) ; v1(2369,2084) 2422,2084 2460,2046 2743,2046 v1(2743,2048)
GPIO3: P2.18 U1.3 | length 1470
  1 w8: v1(2726,1889) 2721,1889 2721,2443 2730.13,2452.13 U1.3 ; v1(3263,2000) v1(3497,2000)
  4 w8: v1(2726,1889) 3132,1889 3243,2000 v1(3263,2000) ; P2.18 v1(3497,2000)
MISO: P1.20 U1.9 | length 1675
  1 w8: v1(2298,1950) 2363,1950 v1(2409,1996) ; U1.9 2889.1,2491.1 2896.9,2491.1 2944,2444 3028,2444 3036,2452 v1(3135,2452)
  4 w8: P1.20 v1(2298,1950) ; v1(2409,1996) 2409,1995 2423,1981 3085,1981 3144,2040 3144,2441 3133,2452 v1(3135,2452)
MOSI: P1.18 U1.7 | length 1587.6
  1 w8: v1(2298,2000) 2298,1997 2367,1997 2420,2050 v1(2423,2050) ; U1.7 2808.87,2460.13 2818,2451 2891,2451 2934,2408 3093,2408 v1(3093,2404)
  4 w8: P1.18 v1(2298,2000) ; v1(2423,2050) 2423,2052 2454,2021 3057,2021 3098,2062 3098,2404 v1(3093,2404)
RESET: P2.15 U1.2 | length 1248.1
  1 w8: v1(2698,1913) 2698,1919 2700,1921 2700,2444.63 2710,2454.63 2710,2471.19 U1.2
  4 w8: v1(2698,1913) 3120,1913 3256,2049 3325,2049 P2.15
SCLK: P1.16 U1.8 | length 1611.8
  1 w8: v1(2297,2050) v1(2373,2050) ; U1.8 2894.37,2471 2937.37,2428 3114,2428 3117,2425 v1(3119,2425)
  4 w8: P1.16 v1(2297,2050) ; v1(2373,2050) 2390,2050 2439,2001 3070,2001 3121,2052 3121,2425 v1(3119,2425)
VDD_REG: C11.2 C51.2 C52.1 C53.1 C121.2 C131.2 C151.2 C171.1 C172.1 C173.2 C221.1 C251.2 C271.2 C281.2 L1.2 R171.2 R322.2 U1.1 U1.5 U1.12 U1.13 U1.15 U1.22 U1.25 U1.27 U1.28 U2.5 | length 2076.3
  1 w8: v1(2999,2375) 2999,2352 3015,2336 v1(3012,2336)
  1 w10: v1(2516,2594) 2511,2594 2520,2585 2552,2585 ; C251.2 2610,2680.25 C251.2@2615,2680.25 ; v1(2650,2465) 2667,2448 2667,2447.24 ; v1(2651,2794) 2651,2793.88 2664.88,2780 2679,2780 C221.1 2690,2774 2690,2752.57 2729,2713.57 2729,2711.54 2730.13,2710.41 2730.13,2708.87 U1.22 ; U1.28 2620.94,2589.94 2591,2560 C281.2 2572,2565 2552,2585 ; U1.27 2597.38,2609.62 C271.2 2597,2607 2575,2585 2573.88,2585 2552,2585 ; U1.25 2619.35,2680.25 C251.2@2615,2680.25 ; v1(2652.25,2680.25) C251.2@2615,2680.25 ; C11.2 2667,2447.24 ; U1.1 2667,2447.24 ; C51.2 2769.5,2420.7 C51.2@2769.5,2421 ; U1.5 C51.2@2769.5,2421 ; v1(2824,2342) 2815.65,2342 2815.65,2378.06 2769.5,2424.21 C51.2@2769.5,2421 ; v1(2842,2378) 2852.89,2378 v1@2848.84,2373.95 ; v1(2844,2307) 2844,2314 2871,2341 2895,2341 2895,2338 v1(2865,2338) ; U1.12 2896.75,2570.25 2930,2537 C121.2 2937,2526 2960,2503 v1(2973,2503) ; U1.13 C131.2@2923,2590 ; U1.15 2878.72,2629.31 2909.42,2660 C151.2@2920,2660 ; v1(2891,2672) 2891,2673 2904,2660 2913,2660 ; v1(2897,2376) 2924,2376 ; v1(2921,2337) 2950.53,2337 ; C131.2 C131.2@2923,2590 ; v1(2950,2375) v1@2950.06,2375.06 ; v1(3013,2571) 3007,2571 3001,2565 2944,2565 2923,2586 C131.2@2923,2590 ; 2913,2660 C151.2 C151.2@2920,2660 ; 2913,2660 C151.2@2920,2660
  1 w12: v1(2427,2319) R322.2 ; C173.2 R171.2 C172.1 ; v1(3074,2679) 3075,2680 C172.1 ; C171.1 C172.1
  1 w20: v1(2817,2279) 2817,2232 2911,2138 L1.2 2874,2112 C53.1 ; v1(2877,2283) 2887,2273 2943,2273 C52.1 2943,2274 U2.5
  3 w8: v1(2817,2279) 2844,2306 v1(2844,2307)
  3 w12: 2977.69,2569.38 3011.38,2569.38 v1(3013,2571)
  3 w20: 2484,2594 v1(2516,2594)
  other v1: 2972,2337
pads on no net: FM1.1 FM2.1 FM3.1 P1.2 P1.3 P1.4 P1.5 P1.6 P1.7 P1.8 P1.9 P1.11 P1.13 P1.15 P1.17 P1.21 P1.22 P2.1 P2.3 P2.4 P2.5 P2.6 P2.8 P2.10 P2.11 P2.12 P2.13 P2.14 P2.16 P2.17 P2.19 P2.20 P2.21 P2.22 U1.16 X2.1

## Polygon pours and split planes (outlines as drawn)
AGND on 3 "L3_GNE" (solid, remove dead copper, pour order 2): 1997.2,3196.4 2777.61,3196.16 3538.2,3196.16 3538.7,3196.45 3538.7,1806.9 1998.45,1806.9
VDD_REG on 3 "L3_VDD_REG" (solid, remove dead copper, pour order 14): 2416.03,2840.5 3085.7,2840.5 3085.7,2756.79 3085.49,2248.25 2415.6,2248.25
AGND on 1 "L1_GND2" (solid, remove dead copper, pour order 4): 3548.5,2803.6 3140.8,2803.6 3141.2,2688.9 3017.3,2688.1 3017.3,2688.9 2923.2,2688.9 2924.51,2612.49 2921.54,2443.44 2613.5,2443.44 2613.1,1793.9 2925.2,1794.4 3548.8,1796
AGND on 1 "L1_GND1" (solid, remove dead copper, pour order 6): 3402.4,2930.1 2781.6,2930.1 2781.6,2854.5 2781.5,2854.4 2742.1,2854.5 2742.1,2822.4 2627,2822.5 2626.5,2446.25 1999.25,2446.5 1999.8,3195.77 3550.4,3196 3550.6,2705.1 3402.4,2705.1
VDD_REG on 1 "L1_VDD_VREG" (solid, remove dead copper, pour order 8): 2802.1,2264 3027,2264 3027,2392.5 2802.1,2392.5 2802.77,2328.8
AGND on 1 "L1_GND5" (solid, remove dead copper, pour order 10): 1999.75,2451.75 2440.5,2452.25 2480,2452.25 2480,2190 2635,2190 2635.25,2189.75 2635.5,1794.75 1999.75,1794.75
no net on 1 "TEMPLATE1" (solid, remove dead copper, shelved, pour order 12): 3163,2350.2 3169,2350.2 3169,2352.2 3163,2352.2
AGND on 1 "L1_GND_XOSC" (solid, remove dead copper, shelved, pour order 16): 2568.25,2497.58 2479,2497.58 2479,2389 2568.25,2389
no net on 1 "TEMPLATE0" (solid, remove dead copper, shelved, pour order 18): 2373.1,2322.2 3217,2322.2 3217,2952.1 2373.1,2952.1
AGND on 4 "L4_GND" (solid, remove dead copper, pour order 20): 2000,1794.5 3550.5,1794.5 3550.5,3196 2000,3196
AGND on 2 "L2_GND" (solid, remove dead copper, pour order 22): 2003,3191.5 2783.41,3191.26 3544,3191.26 3544.5,3191.55 3544.5,1802 2004.25,1802

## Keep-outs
Keep-Out Layer:
  the board outline again, w1

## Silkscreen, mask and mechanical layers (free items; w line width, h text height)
Top Silk:
  drawing of 569 lines, arcs and shapes, not listed
  text "CC112xEM" at 2273.2,2635.7 h35 r90
  text "Rev 1.1" at 2325.3,2633.2 h24.5 r90
Bottom silk:
  region: 3132.86,2316.3 3205.7,2316.3 3205.7,2292.68 3132.86,2292.68
  region: 3084.05,2387.56 3102.16,2387.56 3102.16,2417.48 3084.05,2417.48
  region: 3044.28,2386.38 3249.01,2386.38 3249.01,2376.53 3044.28,2376.53
  region: 3232.47,2314.72 3268.69,2314.72 3268.69,2353.7 3232.47,2353.7
  region: 3087.98,2089.53 3109.64,2089.53 3109.64,2106.06 3087.98,2106.06
  region: 3138.38,2401.34 3186.41,2401.34 3186.41,2418.27 3138.38,2418.27
  region: 2948.22,2459.61 3339.56,2047.79 3333.26,2041.5 2948.61,2447.4
  region: 3353.73,2460 2962.39,2048.19 2968.69,2041.89 3353.34,2447.79
  region: 3259.24,2374.57 cw(c3259.24,2390.31) 3259.24,2406.06 cw(c3259.24,2390.31)
  region: 3062.98,2384.61 3088.2,2103.11 3201.76,2103.11 3209,2103.14 cw(c3222.84,2115.58) 3225.13,2134.05 3225.68,2139.79 3225.25,2134.88 3248.02,2384.61
  region: 3066.33,2384.41 3066.33,2390.31 3066.72,2390.31 cw(c3138.27,2299.75) 3134.83,2415.12 3190.74,2415.12 cw(c3188.31,2344.04) 3242.31,2390.31 3242.31,2384.41
  region: 3223.02,2091.1 3223.81,2091.1 ccw(c3223.81,2114.72) 3247.43,2114.72 3247.43,2116.3 ccw(c3223.81,2116.3) 3223.81,2139.92 3223.02,2139.92 3223.02,2134.01 3224.2,2134.01 cw(c3224.21,2115.92) 3242.31,2115.9 cw(c3224.16,2114.77) 3223.02,2096.61
  region: 3223.02,2107.24 cw(c3223.02,2115.9) 3223.02,2124.57 cw(c3223.02,2115.9)
  region: 3223.02,2139.92 3222.23,2139.92 ccw(c3222.23,2116.3) 3198.61,2116.3 3198.61,2114.72 ccw(c3222.23,2114.72) 3222.23,2091.1 3223.02,2091.1 3223.02,2097.01 3221.84,2097.01 cw(c3221.83,2115.11) 3203.73,2115.12 cw(c3221.89,2116.25) 3223.02,2134.41
Drill Drawing:
  drawing of 406 lines, arcs and shapes, not listed

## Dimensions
1982,3193 to 1982,1793 on Unassigned
1999,2018 to 3549,2018 on Unassigned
